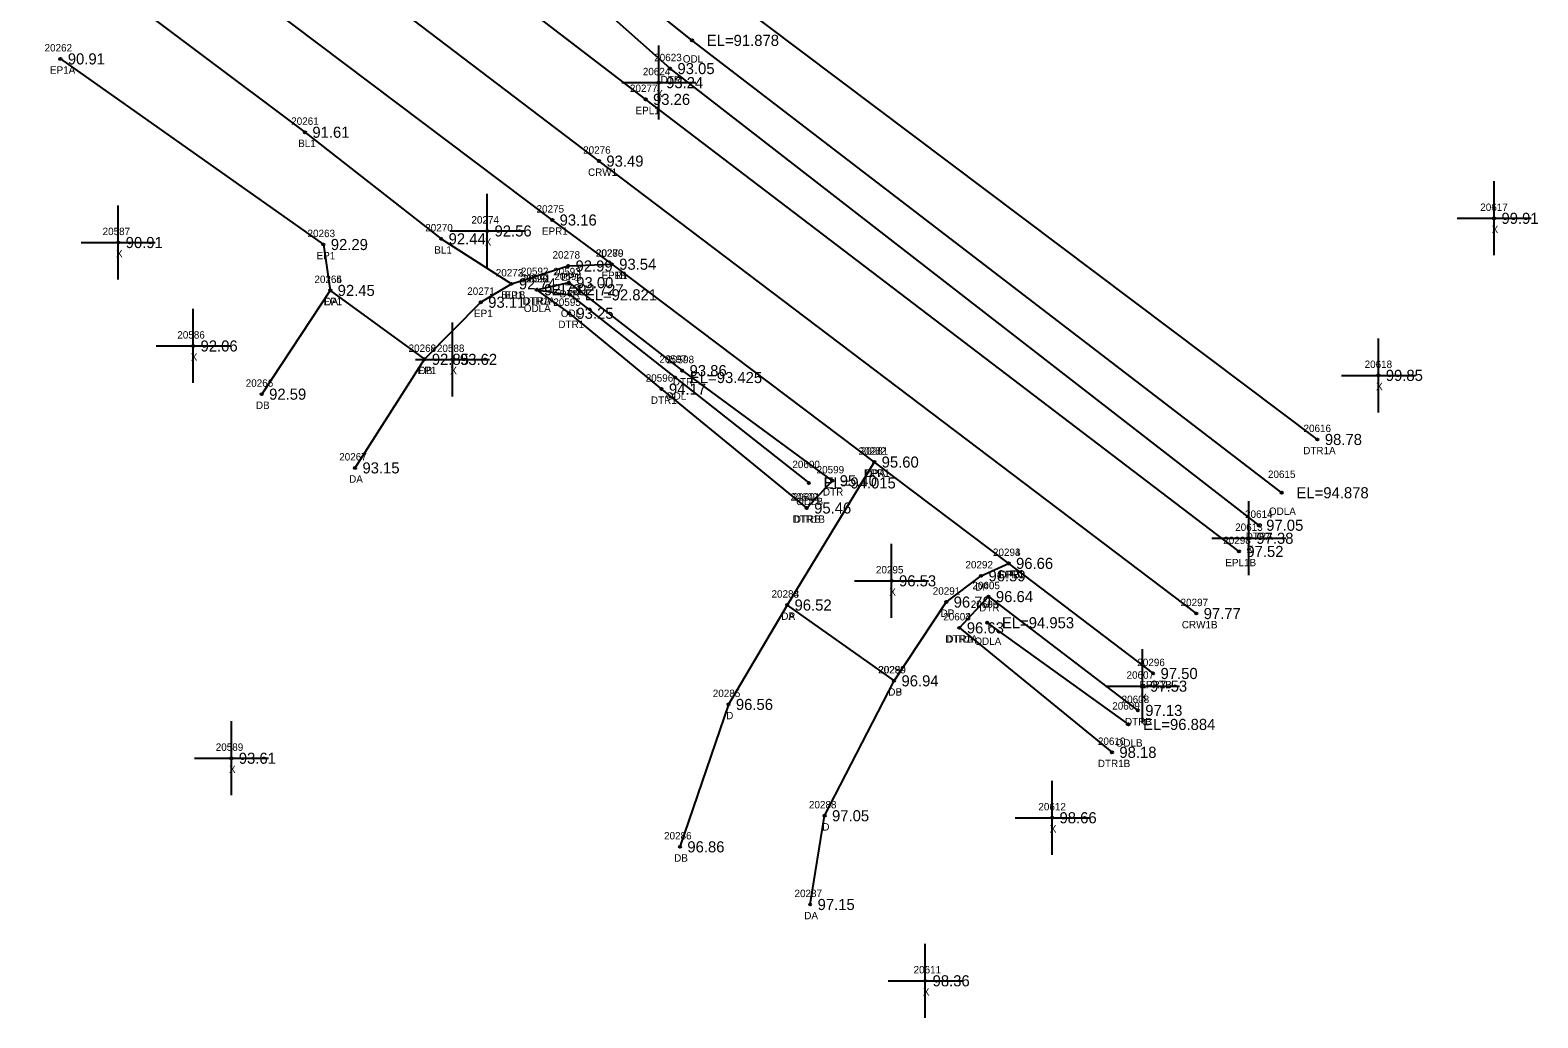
# Model space of a CAD drawing. Extents: x 2530197 to 2532051, y 935230 to 936631.
# Drawn here: x 2531847.5 to 2532051.3, y 936097.5 to 936230.9 of the extents above; entities that cross this region are included whole.
import ezdxf

# ---------------------------------------------------------------- set-up
doc = ezdxf.new("R2010")
doc.units = 0
for name, color, linetype in [('RD_DTM_BkLn1', 7, 'Continuous'), ('RD_DTM_BkLn_txCode', 7, 'Continuous'), ('RD_EX_Driveway', 7, 'Continuous'), ('RD_EX_Driveway_txCode', 7, 'Continuous'), ('RD_EX_H2O', 7, 'Continuous'), ('RD_EX_H2O_txCode', 7, 'Continuous'), ('RD_EX_Misc', 7, 'Continuous'), ('RD_EX_Misc_txCode', 7, 'Continuous'), ('RD_EX_Road', 7, 'Continuous'), ('RD_EX_Road_txCode', 7, 'Continuous'), ('RD_EX_TX_Driveway_ELEV', 7, 'Continuous'), ('RD_EX_TX_H2O_ELEV', 7, 'Continuous'), ('RD_EX_TX_Misc_ELEV', 7, 'Continuous'), ('RD_EX_TX_Road_ELEV', 7, 'Continuous'), ('RD_HC_Survey_ELEV', 7, 'Continuous'), ('RD_HC_Survey_txCode', 7, 'Continuous'), ('RD_SMD_Locator', 7, 'Continuous')]:
    doc.layers.add(name, color=color, linetype=linetype)

msp = doc.modelspace()

# ---------------------------------------------------------------- linework, layer by layer
at = {"layer": 'RD_DTM_BkLn1'}
for points in [[(2531766.68, 936333.11), (2531794.16, 936312.25), (2531844.23, 936274.13), (2531924.38, 936213.25), (2532005.14, 936152.12)], [(2531839.12, 936251.81), (2531841.44, 936249.51), (2531884.63, 936217.15), (2531903.05, 936202.75), (2531912.55, 936196.67)]]:
    msp.add_lwpolyline(points, dxfattribs=at)
at = {"layer": 'RD_EX_Driveway'}
for p, q in [((2531888.05, 936195.78), (2531878.78, 936181.76)), ((2531891.4, 936171.8), (2531900.78, 936186.47))]:
    msp.add_line(p, q, dxfattribs=at)
for points in [[(2531961.6, 936172.59), (2531949.82, 936153.27), (2531964.28, 936143.03), (2531971.34, 936153.67), (2531976.04, 936157.22), (2531979.77, 936158.9)], [(2531949.82, 936153.27), (2531941.89, 936139.84), (2531935.33, 936120.6)], [(2531952.94, 936112.81), (2531954.89, 936124.8), (2531964.28, 936143.03)]]:
    msp.add_lwpolyline(points, dxfattribs=at)
at = {"layer": 'RD_EX_H2O'}
for p, q in [((2531973.11, 936150.19), (2531993.74, 936133.37)), ((2531976.86, 936150.88), (2531995.96, 936137.14))]:
    msp.add_line(p, q, dxfattribs=at)
for points in [[(2532013.59, 936164.05), (2531933.99, 936225.75), (2531895.93, 936259.56), (2531897, 936261.91), (2531899.89, 936263.49), (2531899.92, 936263.44)], [(2532021.52, 936175.64), (2531941.85, 936235.58), (2531899.92, 936263.44)], [(2532016.69, 936168.44), (2531936.96, 936229.56), (2531899.85, 936259.16)], [(2531915.95, 936195.86), (2531920.31, 936196.83), (2531935.63, 936184.94), (2531955.93, 936170.06), (2531952.47, 936166.38)], [(2531915.95, 936195.86), (2531920.47, 936195.18), (2531934.68, 936184.01), (2531952.75, 936169.77)], [(2531915.95, 936195.86), (2531920.33, 936192.69), (2531932.84, 936182.45), (2531952.47, 936166.38)], [(2531973.11, 936150.19), (2531977.05, 936154.41), (2531997.24, 936139.03)]]:
    msp.add_lwpolyline(points, dxfattribs=at)
at = {"layer": 'RD_EX_Misc'}
for p, q in [((2531932.46, 936218.85), (2531932.46, 936228.85)), ((2531927.46, 936223.85), (2531937.46, 936223.85)), ((2532045.4, 936200.52), (2532045.4, 936210.52)), ((2531859.39, 936197.25), (2531859.39, 936207.25)), ((2531909.26, 936198.81), (2531909.26, 936208.81)), ((2532040.4, 936205.52), (2532050.4, 936205.52)), ((2531904.26, 936203.81), (2531914.26, 936203.81)), ((2531854.39, 936202.25), (2531864.39, 936202.25)), ((2531869.51, 936183.27), (2531869.51, 936193.27)), ((2531904.59, 936181.46), (2531904.59, 936191.46)), ((2532029.76, 936179.3), (2532029.76, 936189.3)), ((2531864.51, 936188.27), (2531874.51, 936188.27)), ((2531899.59, 936186.46), (2531909.59, 936186.46)), ((2532024.76, 936184.3), (2532034.76, 936184.3)), ((2532012.26, 936157.29), (2532012.26, 936167.29)), ((2531963.95, 936151.54), (2531963.95, 936161.54)), ((2532007.26, 936162.29), (2532017.26, 936162.29)), ((2531958.95, 936156.54), (2531968.95, 936156.54)), ((2531997.89, 936137.31), (2531997.89, 936147.31)), ((2531992.89, 936142.31), (2532002.89, 936142.31)), ((2531874.68, 936127.57), (2531874.68, 936137.57)), ((2531869.68, 936132.57), (2531879.68, 936132.57)), ((2531985.65, 936119.53), (2531985.65, 936129.53)), ((2531980.65, 936124.53), (2531990.65, 936124.53)), ((2531968.49, 936097.5), (2531968.49, 936107.5)), ((2531963.49, 936102.5), (2531973.49, 936102.5))]:
    msp.add_line(p, q, dxfattribs=at)
at = {"layer": 'RD_EX_Road'}
for points in [[(2531788.67, 936375.53), (2531784.05, 936361.55), (2531786.68, 936344.28), (2531790.66, 936334.1), (2531795.41, 936327.11), (2531801.08, 936320.84), (2531849.6, 936283.17), (2531876.01, 936264.22), (2531894.71, 936249.13), (2531930.69, 936221.59), (2532010.91, 936160.51)], [(2531730.37, 936304.55), (2531747.09, 936311.1), (2531758.83, 936311.42), (2531770.03, 936309.95), (2531779.92, 936307.38), (2531789.77, 936300.82), (2531836.93, 936266.34), (2531918.06, 936205.29), (2531926.11, 936199.32), (2531961.6, 936172.59), (2531979.77, 936158.9), (2531999.31, 936144.02)], [(2531851.56, 936227.06), (2531887.12, 936201.98), (2531888.05, 936195.78), (2531900.78, 936186.47), (2531908.4, 936194.18), (2531912.55, 936196.67), (2531920.21, 936199.08), (2531926.11, 936199.32)]]:
    msp.add_lwpolyline(points, dxfattribs=at)
at = {"layer": 'RD_SMD_Locator'}
for centre in [(2531936.96, 936229.56), (2531851.56, 936227.06), (2531933.99, 936225.75), (2531932.46, 936223.85), (2531930.69, 936221.59), (2531884.63, 936217.15), (2531924.38, 936213.25), (2531918.06, 936205.29), (2532045.4, 936205.52), (2531909.26, 936203.81), (2531859.39, 936202.25), (2531887.12, 936201.98), (2531903.05, 936202.75), (2531920.21, 936199.08), (2531926.11, 936199.32), (2531926.11, 936199.32), (2531920.31, 936196.83), (2531888.05, 936195.78), (2531888.05, 936195.78), (2531912.55, 936196.67), (2531912.55, 936196.67), (2531915.95, 936195.86), (2531915.95, 936195.86), (2531915.95, 936195.86), (2531920.47, 936195.18), (2531908.4, 936194.18), (2531920.33, 936192.69), (2531869.51, 936188.27), (2531900.78, 936186.47), (2531900.78, 936186.47), (2531904.59, 936186.46), (2531935.63, 936184.94), (2531934.68, 936184.01), (2532029.76, 936184.3), (2531878.78, 936181.76), (2531932.84, 936182.45), (2532021.52, 936175.64), (2531961.6, 936172.59), (2531961.6, 936172.59), (2531891.4, 936171.8), (2531952.75, 936169.77), (2531955.93, 936170.06), (2532016.69, 936168.44), (2531952.47, 936166.38), (2531952.47, 936166.38), (2532012.26, 936162.29), (2532013.59, 936164.05), (2532010.91, 936160.51), (2531979.77, 936158.9), (2531979.77, 936158.9), (2531963.95, 936156.54), (2531976.04, 936157.22), (2531977.05, 936154.41), (2531949.82, 936153.27), (2531949.82, 936153.27), (2531971.34, 936153.67), (2532005.14, 936152.12), (2531973.11, 936150.19), (2531973.11, 936150.19), (2531976.86, 936150.88), (2531999.31, 936144.02), (2531964.28, 936143.03), (2531964.28, 936143.03), (2531997.89, 936142.31), (2531941.89, 936139.84), (2531997.24, 936139.03), (2531995.96, 936137.14), (2531874.68, 936132.57), (2531993.74, 936133.37), (2531954.89, 936124.8), (2531985.65, 936124.53), (2531935.33, 936120.6), (2531952.94, 936112.81), (2531968.49, 936102.5)]:
    msp.add_circle(centre, 0.15, dxfattribs=at)

# ---------------------------------------------------------------- texts
at = {"layer": 'RD_DTM_BkLn_txCode'}
for s, p in [('20261', (2531882.77, 936218.15)), ('BL1', (2531883.71, 936215.15)), ('20270', (2531900.89, 936203.75)), ('BL1', (2531902.12, 936200.75)), ('20273', (2531910.43, 936197.67)), ('BL1B', (2531911.16, 936194.67))]:
    msp.add_text(s, height=1, dxfattribs=at).set_placement(p)
at = {"layer": 'RD_EX_Driveway_txCode'}
for s, p in [('20265', (2531885.91, 936196.78)), ('DA', (2531887.26, 936193.78)), ('20269', (2531898.64, 936187.47)), ('DB', (2531900, 936184.47)), ('20266', (2531876.62, 936182.76)), ('DB', (2531878, 936179.76)), ('20282', (2531959.49, 936173.59)), ('20267', (2531889.26, 936172.8)), ('DA', (2531890.6, 936169.8)), ('DPA', (2531960.34, 936170.59)), ('20293', (2531977.65, 936159.9)), ('20292', (2531973.93, 936158.22)), ('DP', (2531975.26, 936155.22)), ('DPB', (2531978.51, 936156.9)), ('20283', (2531947.71, 936154.27)), ('20284', (2531947.71, 936154.27)), ('20291', (2531969.51, 936154.67)), ('DA', (2531949.03, 936151.27)), ('DP', (2531949.04, 936151.27)), ('DP', (2531970.56, 936151.67)), ('20290', (2531962.12, 936144.03)), ('20289', (2531962.16, 936144.03)), ('DB', (2531963.5, 936141.03)), ('DP', (2531963.5, 936141.03)), ('20285', (2531939.77, 936140.84)), ('D', (2531941.58, 936137.84)), ('20288', (2531952.77, 936125.8)), ('D', (2531954.58, 936122.8)), ('20286', (2531933.18, 936121.6)), ('DB', (2531934.55, 936118.6)), ('20287', (2531950.82, 936113.81)), ('DA', (2531952.14, 936110.81))]:
    msp.add_text(s, height=1, dxfattribs=at).set_placement(p)
at = {"layer": 'RD_EX_H2O_txCode'}
for s, p in [('20623', (2531931.85, 936226.75)), ('ODL', (2531935.72, 936226.56)), ('DTR', (2531932.72, 936223.75)), ('20590', (2531913.79, 936196.86)), ('20592', (2531913.83, 936197.86)), ('20591', (2531914.11, 936196.86)), ('20593', (2531918.19, 936197.83)), ('20594', (2531918.35, 936197.18)), ('DTR', (2531919.04, 936194.83)), ('DTR1A', (2531914.03, 936193.86)), ('ODLA', (2531914.22, 936192.86)), ('DTRA', (2531914.19, 936193.86)), ('20595', (2531918.21, 936193.69)), ('ODL', (2531919.22, 936192.18)), ('DTR1', (2531918.89, 936190.69)), ('20597', (2531932.56, 936186.01)), ('20598', (2531933.52, 936185.94)), ('20596', (2531930.7, 936183.45)), ('DTR', (2531934.37, 936182.94)), ('DTR1', (2531931.4, 936180.45)), ('ODL', (2531933.43, 936181.01)), ('20616', (2532019.64, 936176.64)), ('DTR1A', (2532019.6, 936173.64)), ('20600', (2531950.53, 936171.77)), ('20599', (2531953.81, 936171.06)), ('20615', (2532014.83, 936170.44)), ('DTR', (2531954.66, 936168.06)), ('20602', (2531950.29, 936167.38)), ('20601', (2531950.57, 936167.38)), ('ODLB', (2531951.04, 936166.77)), ('ODLA', (2532014.96, 936165.44)), ('DTR1B', (2531950.56, 936164.38)), ('DTRB', (2531950.73, 936164.38)), ('20614', (2532011.73, 936165.05)), ('DTRA', (2532011.83, 936162.05)), ('20605', (2531974.87, 936155.41)), ('20603', (2531970.93, 936151.19)), ('20604', (2531970.93, 936151.19)), ('20606', (2531974.65, 936152.88)), ('DTR', (2531975.79, 936152.41)), ('DTR1A', (2531971.19, 936148.19)), ('DTRA', (2531971.36, 936148.19)), ('ODLA', (2531975.13, 936147.88)), ('20609', (2531993.78, 936139.14)), ('20608', (2531995.05, 936140.03)), ('DTRB', (2531995.5, 936137.03)), ('20610', (2531991.84, 936134.37)), ('ODLB', (2531994.24, 936134.14)), ('DTR1B', (2531991.83, 936131.37))]:
    msp.add_text(s, height=1, dxfattribs=at).set_placement(p)
at = {"layer": 'RD_EX_Misc_txCode'}
for s, p in [('20624', (2531930.31, 936224.85)), ('X', (2531932.14, 936221.85)), ('20617', (2532043.54, 936206.52)), ('20274', (2531907.14, 936204.81)), ('20587', (2531857.27, 936203.25)), ('X', (2532045.08, 936203.52)), ('X', (2531859.08, 936200.25)), ('X', (2531908.94, 936201.81)), ('20586', (2531867.37, 936189.27)), ('X', (2531869.19, 936186.27)), ('20588', (2531902.47, 936187.46)), ('X', (2531904.27, 936184.46)), ('20618', (2532027.9, 936185.3)), ('X', (2532029.45, 936182.3)), ('20613', (2532010.4, 936163.29)), ('X', (2532011.94, 936160.29)), ('20295', (2531961.83, 936157.54)), ('X', (2531963.63, 936154.54)), ('20607', (2531995.71, 936143.31)), ('X', (2531997.57, 936140.31)), ('20589', (2531872.57, 936133.57)), ('X', (2531874.37, 936130.57)), ('20612', (2531983.79, 936125.53)), ('X', (2531985.33, 936122.53)), ('20611', (2531966.92, 936103.5)), ('X', (2531968.18, 936100.5))]:
    msp.add_text(s, height=1, dxfattribs=at).set_placement(p)
at = {"layer": 'RD_EX_Road_txCode'}
for s, p in [('20262', (2531849.42, 936228.06)), ('EP1A', (2531850.15, 936225.06)), ('20277', (2531928.57, 936222.59)), ('EPL1', (2531929.32, 936219.59)), ('20275', (2531915.94, 936206.29)), ('20263', (2531884.98, 936202.98)), ('EPR1', (2531916.67, 936203.29)), ('20278', (2531918.1, 936200.08)), ('20280', (2531923.95, 936200.32)), ('20279', (2531923.99, 936200.32)), ('EP1', (2531886.2, 936199.98)), ('20264', (2531885.91, 936196.78)), ('20272', (2531910.43, 936197.67)), ('EP1', (2531919.29, 936197.08)), ('EP1B', (2531924.72, 936197.32)), ('EPR1', (2531924.72, 936197.32)), ('20271', (2531906.57, 936195.18)), ('EP1', (2531911.63, 936194.67)), ('EP1', (2531887.13, 936193.78)), ('EP1', (2531907.48, 936192.18)), ('20268', (2531898.64, 936187.47)), ('EP1', (2531899.86, 936184.47)), ('20281', (2531959.77, 936173.59)), ('EPR1', (2531960.21, 936170.59)), ('20298', (2532008.79, 936161.51)), ('20294', (2531977.65, 936159.9)), ('EPL1B', (2532009.07, 936158.51)), ('EPR1', (2531978.37, 936156.9)), ('20296', (2531997.17, 936145.02)), ('EPR1B', (2531997.45, 936142.02))]:
    msp.add_text(s, height=1, dxfattribs=at).set_placement(p)
at = {"layer": 'RD_EX_TX_Driveway_ELEV'}
for s, p in [('92.45', (2531889.05, 936195.03)), ('92.85', (2531901.78, 936185.72)), ('92.59', (2531879.78, 936181.01)), ('93.15', (2531892.4, 936171.05)), ('95.60', (2531962.6, 936171.84)), ('96.66', (2531980.77, 936158.15)), ('96.59', (2531977.04, 936156.47)), ('96.70', (2531972.34, 936152.92)), ('96.52', (2531950.82, 936152.52)), ('96.52', (2531950.82, 936152.52)), ('96.94', (2531965.28, 936142.28)), ('96.94', (2531965.28, 936142.28)), ('96.56', (2531942.89, 936139.09)), ('97.05', (2531955.89, 936124.05)), ('96.86', (2531936.33, 936119.85)), ('97.15', (2531953.94, 936112.06))]:
    msp.add_text(s, height=1.5, dxfattribs=at).set_placement(p)
at = {"layer": 'RD_EX_TX_H2O_ELEV'}
for s, p in [('EL=91.878', (2531938.96, 936228.81)), ('93.05', (2531934.99, 936225)), ('93.00', (2531921.31, 936196.08)), ('92.73', (2531916.95, 936195.11)), ('92.73', (2531916.95, 936195.11)), ('EL=92.727', (2531917.95, 936195.11)), ('EL=92.821', (2531922.47, 936194.43)), ('93.25', (2531921.33, 936191.94)), ('93.86', (2531936.63, 936184.19)), ('EL=93.425', (2531936.68, 936183.26)), ('94.17', (2531933.84, 936181.7)), ('98.78', (2532022.52, 936174.89)), ('EL=94.015', (2531954.75, 936169.02)), ('95.40', (2531956.93, 936169.31)), ('EL=94.878', (2532018.69, 936167.69)), ('95.46', (2531953.47, 936165.63)), ('95.46', (2531953.47, 936165.63)), ('97.05', (2532014.59, 936163.3)), ('96.64', (2531978.05, 936153.66)), ('96.63', (2531974.11, 936149.44)), ('96.63', (2531974.11, 936149.44)), ('EL=94.953', (2531978.86, 936150.13)), ('EL=96.884', (2531997.96, 936136.39)), ('97.13', (2531998.24, 936138.28)), ('98.18', (2531994.74, 936132.62))]:
    msp.add_text(s, height=1.5, dxfattribs=at).set_placement(p)
at = {"layer": 'RD_EX_TX_Misc_ELEV'}
for s, p in [('93.24', (2531933.46, 936223.1)), ('91.61', (2531885.63, 936216.4)), ('99.91', (2532046.4, 936204.77)), ('92.44', (2531904.05, 936202)), ('92.56', (2531910.26, 936203.06)), ('90.91', (2531860.39, 936201.5)), ('92.74', (2531913.55, 936195.92)), ('92.06', (2531870.51, 936187.52)), ('93.62', (2531905.59, 936185.71)), ('99.85', (2532030.76, 936183.55)), ('97.38', (2532013.26, 936161.54)), ('96.53', (2531964.95, 936155.79)), ('97.53', (2531998.89, 936141.56)), ('93.61', (2531875.68, 936131.82)), ('98.66', (2531986.65, 936123.78)), ('98.36', (2531969.49, 936101.75))]:
    msp.add_text(s, height=1.5, dxfattribs=at).set_placement(p)
at = {"layer": 'RD_EX_TX_Road_ELEV'}
for s, p in [('90.91', (2531852.56, 936226.31)), ('93.26', (2531931.69, 936220.84)), ('93.16', (2531919.06, 936204.54)), ('92.29', (2531888.12, 936201.23)), ('92.99', (2531921.21, 936198.33)), ('93.54', (2531927.11, 936198.57)), ('93.54', (2531927.11, 936198.57)), ('92.74', (2531913.55, 936195.92)), ('92.45', (2531889.05, 936195.03)), ('93.11', (2531909.4, 936193.43)), ('92.85', (2531901.78, 936185.72)), ('95.60', (2531962.6, 936171.84)), ('97.52', (2532011.91, 936159.76)), ('96.66', (2531980.77, 936158.15)), ('97.50', (2532000.31, 936143.27))]:
    msp.add_text(s, height=1.5, dxfattribs=at).set_placement(p)
at = {"layer": 'RD_HC_Survey_ELEV'}
for s, p in [('93.49', (2531925.38, 936212.5)), ('97.77', (2532006.14, 936151.37))]:
    msp.add_text(s, height=1.5, dxfattribs=at).set_placement(p)
at = {"layer": 'RD_HC_Survey_txCode'}
for s, p in [('20276', (2531922.24, 936214.25)), ('CRW1', (2531922.9, 936211.25)), ('20297', (2532003.02, 936153.12)), ('CRW1B', (2532003.19, 936150.12))]:
    msp.add_text(s, height=1, dxfattribs=at).set_placement(p)

doc.saveas('drawing.dxf')
